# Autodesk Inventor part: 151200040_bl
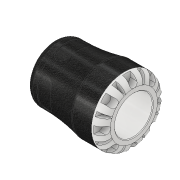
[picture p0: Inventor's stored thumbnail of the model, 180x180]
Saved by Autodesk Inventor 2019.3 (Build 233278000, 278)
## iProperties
Created: 2016-12
Part Number: 151200040_bl
Material: PVC-Piping
Description: PLASSON G-PLASS END CAP 40
Document SubType Name: Modeling
Designer: KIM
Mass: 57.8335 g
Surface Area: 121.129 cm^2
Volume: 41.3096 cm^3
Density: 1.4 g/cm^3
Appearance: Black Cast
Author: KIM
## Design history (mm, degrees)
derived "151200.ipt"
feature "Solid1::151200.ipt" dims "ScaleForDerivedMember" = 10
tag "TaggingFeature1"
body "Solid1"
other parameters: "d0" = 93 [user parameter], "d1" = 30.66 [user parameter], "d6" = 73 [user parameter], "d7" = 80.3 [user parameter], "d8" = 59.5 [user parameter], "d13" = 8 [user parameter], "d14" = 8 [user parameter], "d15" = 0 [user parameter], "d17" = 360 deg [user parameter], "d19" = 8 deg [user parameter], "d20" = 0.8 [user parameter], "d21" = 0.8 [user parameter], "d22" = 8 deg [user parameter], "d24" = 0 [user parameter], "d26" = 360 deg [user parameter], "d32" = 7 [user parameter], "d33" = 7 [user parameter], "d34" = 8.8 [user parameter], "d35" = 14 [user parameter], "d36" = 15.68 [user parameter], "d37" = 0 [user parameter], "d42" = 360 deg [user parameter], "d45" = 11.9 [user parameter], "d46" = 0.8 [user parameter], "d48" = 0 [user parameter], "d49" = 0.7 [user parameter], "H_" = 93 [user parameter], "l_" = 73 [user parameter]
